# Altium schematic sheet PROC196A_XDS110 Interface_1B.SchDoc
size 431 x 279 mm; Date: Not shown in title block; ApprovedBy: Not shown in title block; CheckedBy: Not shown in title block; Author: Not shown in title block; CompanyName: Not shown in title block; Engineer: Not shown in title block; Organization: Not shown in title block; Address1: Not shown in title block; Address2: Not shown in title block; Address3: Not shown in title block; Address4: Not shown in title block; DocumentNumber: 19; Revision: Use project parameter SCH_Rev; SheetNumber: 19; SheetTotal: 25; PageSetup: Record=PageOptions¦CenterHorizontal=True¦CenterVertical=True¦PrintScale=1.00¦XCorrection=1.00¦YCorrection=1.00¦PrintKind=0¦BorderSize=5000000¦LeftOffset=0¦BottomOffset=0¦Orientation=2¦PaperLength=1000¦PaperWidth=1000¦Scale=100¦PaperSource=15¦PrintQuality=600¦MediaType=1¦DitherType=10¦PaperKind=Letter¦PrintScaleMode=1
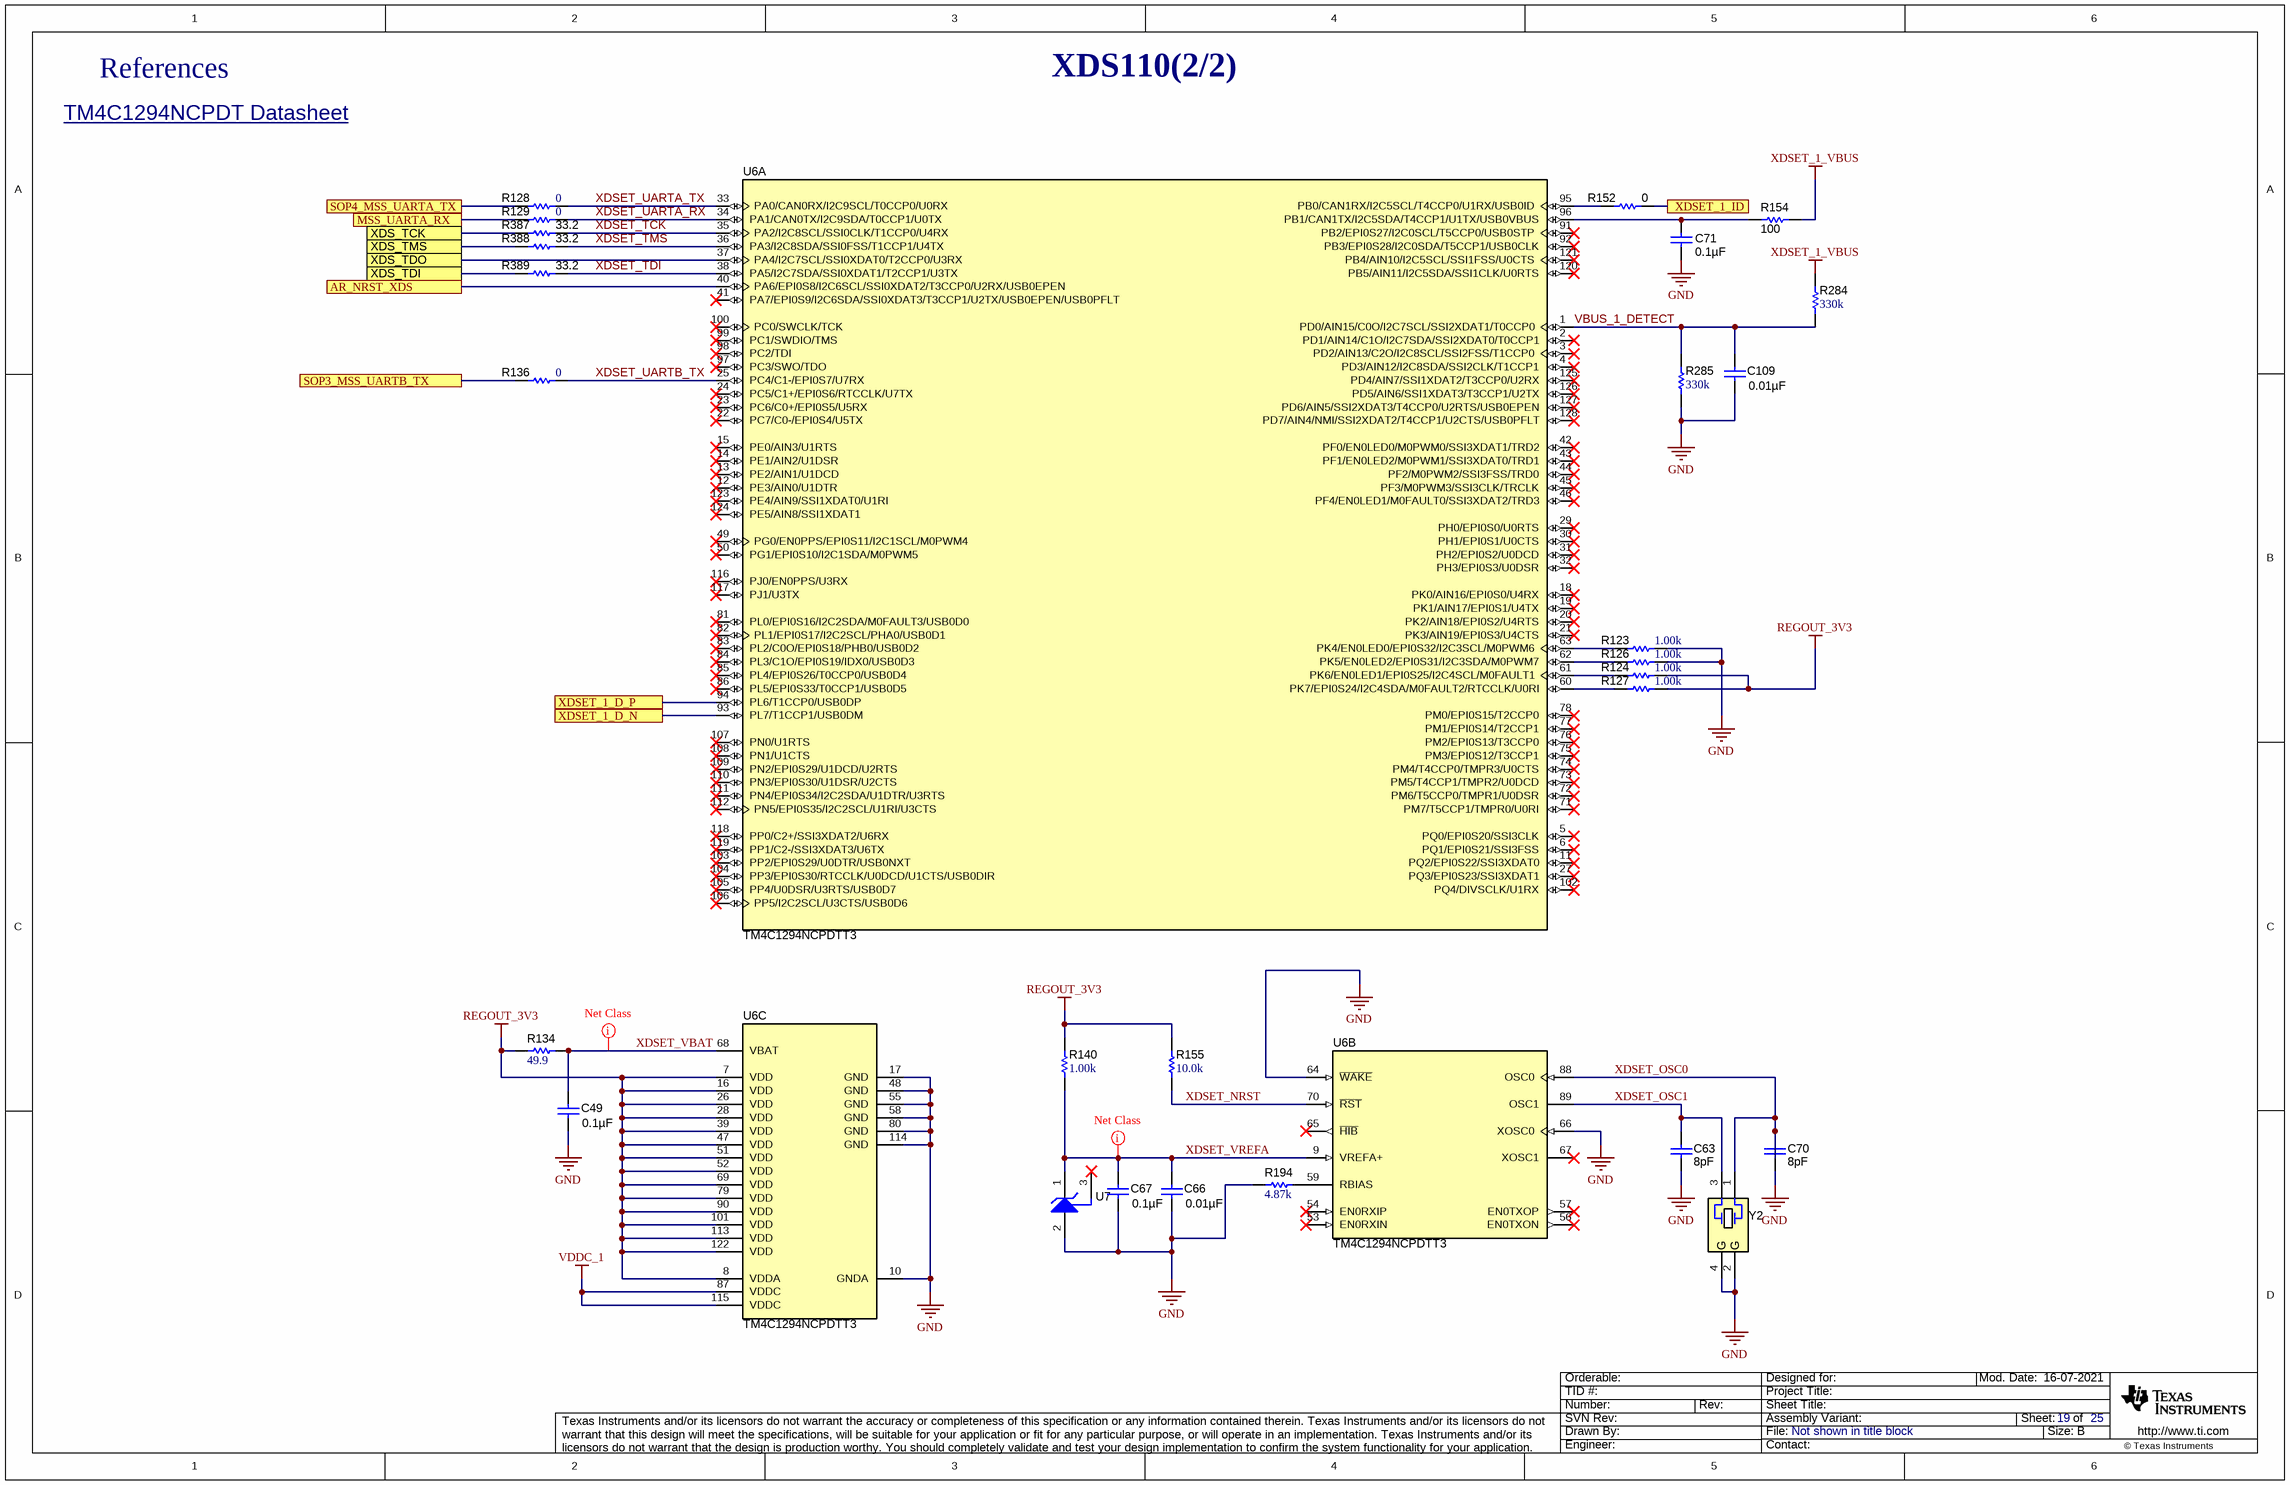
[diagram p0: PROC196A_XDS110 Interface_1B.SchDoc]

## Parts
C49  ValueDisplayed: 0.1µF  [0402L]  (hidden comment: C0402C104K8RACTU)
C63  Cap_F: 8pF  [0402L]  (hidden comment: GCM1555C1H8R0DA16D)
C66  ValueDisplayed: 0.01µF  [0402L]  (hidden comment: C0402C103K4RACTU)
C67  ValueDisplayed: 0.1µF  [0402L]  (hidden comment: C0402C104K8RACTU)
C70  Cap_F: 8pF  [0402L]  (hidden comment: GCM1555C1H8R0DA16D)
C71  ValueDisplayed: 0.1µF  [0402L]  (hidden comment: C0402C104K8RACTU)
C109  ValueDisplayed: 0.01µF  [0402L]  (hidden comment: C0402C103K4RACTU)
R123  ValueDisplayed: 1.00k  [0402L]  (hidden comment: CRCW04021K00FKED)
R124  ValueDisplayed: 1.00k  [0402L]  (hidden comment: CRCW04021K00FKED)
R126  ValueDisplayed: 1.00k  [0402L]  (hidden comment: CRCW04021K00FKED)
R127  ValueDisplayed: 1.00k  [0402L]  (hidden comment: CRCW04021K00FKED)
R128  ValueDisplayed: 0  [0402L]  (hidden comment: ERJ-2GE0R00X)
R129  ValueDisplayed: 0  [0402L]  (hidden comment: ERJ-2GE0R00X)
R134  ValueDisplayed: 49.9  [0402L]  (hidden comment: CRCW040249R9FKED)
R136  ValueDisplayed: 0  [0402L]  (hidden comment: ERJ-2GE0R00X)
R140  ValueDisplayed: 1.00k  [0402L]  (hidden comment: CRCW04021K00FKED)
R152  ValueDisplayed: 0  [0402L]  (hidden comment: ERJ-2GE0R00X)
R154  ValueDisplayed: 100  [0402L]  (hidden comment: ERJ-2GEJ101X)
R155  ValueDisplayed: 10.0k  [0402L]  (hidden comment: CRCW040210K0FKED)
R194  ValueDisplayed: 4.87k  [0402L]  (hidden comment: CRCW04024K87FKED)
R284  ValueDisplayed: 330k  [0402L]  (hidden comment: CRCW0402330KFKED)
R285  ValueDisplayed: 330k  [0402L]  (hidden comment: CRCW0402330KFKED)
R387  ValueDisplayed: 33.2  [0402L]  (hidden comment: CRCW040233R2FKED)
R388  ValueDisplayed: 33.2  [0402L]  (hidden comment: CRCW040233R2FKED)
R389  ValueDisplayed: 33.2  [0402L]  (hidden comment: CRCW040233R2FKED)
U6  TM4C1294NCPDTT3  [PDT0128A]  (parts A,B,C of 3)
U7  LM4040C25QDBZR  [DBZ0003A_N]  (value not drawn)
Y2  NX3225SA-16.000M-STD-CRS-2  [NDK_NX3225SA]  (value not drawn)

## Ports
AR_NRST_XDS, MSS_UARTA_RX, SOP3_MSS_UARTB_TX, SOP4_MSS_UARTA_TX, XDS_TCK, XDS_TDI, XDS_TDO, XDS_TMS, XDSET_1_D_N, XDSET_1_D_P, XDSET_1_ID

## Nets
GND: C49.2 C63.1 C66.1 C67.1 C70.2 C71.1 C109.1 R123.2 R126.2 R194.1 R285.1 U6.10(GNDA) U6.17(GND) U6.48(GND) U6.55(GND) U6.58(GND) U6.64(~{WAKE}) U6.66(XOSC0) U6.80(GND) U6.114(GND) U7.2(ANODE) Y2.2(GND) Y2.4(GND)
REGOUT_3V3: R124.2 R127.2 R134.2 R140.2 R155.2 U6.7(VDD) U6.8(VDDA) U6.16(VDD) U6.26(VDD) U6.28(VDD) U6.39(VDD) U6.47(VDD) U6.51(VDD) U6.52(VDD) U6.69(VDD) U6.79(VDD) U6.90(VDD) U6.101(VDD) U6.113(VDD) U6.122(VDD)
VDDC_1: U6.87(VDDC) U6.115(VDDC)
XDSET_1_VBUS: R154.2 R284.2
AR_NRST_XDS: U6.40(PA6/EPI0S8/I2C6SCL/SSI0XDAT2/T3CCP0/U2RX/USB0EPEN) ; port AR_NRST_XDS
MSS_UARTA_RX: R129.1 ; port MSS_UARTA_RX
SOP3_MSS_UARTB_TX: R136.1 ; port SOP3_MSS_UARTB_TX
SOP4_MSS_UARTA_TX: R128.1 ; port SOP4_MSS_UARTA_TX
VBUS_1_DETECT: C109.2 R284.1 R285.2 U6.1(PD0/AIN15/C0O/I2C7SCL/SSI2XDAT1/T0CCP0)
XDS_TCK: R387.1 ; port XDS_TCK
XDS_TDI: R389.1 ; port XDS_TDI
XDS_TDO: U6.37(PA4/I2C7SCL/SSI0XDAT0/T2CCP0/U3RX) ; port XDS_TDO
XDS_TMS: R388.1 ; port XDS_TMS
XDSET_1_D_N: U6.93(PL7/T1CCP1/USB0DM) ; port XDSET_1_D_N
XDSET_1_D_P: U6.94(PL6/T1CCP0/USB0DP) ; port XDSET_1_D_P
XDSET_1_ID: R152.1 ; port XDSET_1_ID
XDSET_NRST: R155.1 U6.70(~{RST})
XDSET_OSC0: C70.1 U6.88(OSC0) Y2.1
XDSET_OSC1: C63.2 U6.89(OSC1) Y2.3
XDSET_TCK: R387.2 U6.35(PA2/I2C8SCL/SSI0CLK/T1CCP0/U4RX)
XDSET_TDI: R389.2 U6.38(PA5/I2C7SDA/SSI0XDAT1/T2CCP1/U3TX)
XDSET_TMS: R388.2 U6.36(PA3/I2C8SDA/SSI0FSS/T1CCP1/U4TX)
XDSET_UARTA_RX: R129.2 U6.34(PA1/CAN0TX/I2C9SDA/T0CCP1/U0TX)
XDSET_UARTA_TX: R128.2 U6.33(PA0/CAN0RX/I2C9SCL/T0CCP0/U0RX)
XDSET_UARTB_TX: R136.2 U6.25(PC4/C1-/EPI0S7/U7RX)
XDSET_VBAT: C49.1 R134.1 U6.68(VBAT)
XDSET_VREFA: C66.2 C67.2 R140.1 U6.9(VREFA+) U7.1(CATHODE)
NetC71_2: C71.2 R154.1 U6.96(PB1/CAN1TX/I2C5SDA/T4CCP1/U1TX/USB0VBUS)
NetR123_1: R123.1 U6.63(PK4/EN0LED0/EPI0S32/I2C3SCL/M0PWM6)
NetR124_1: R124.1 U6.61(PK6/EN0LED1/EPI0S25/I2C4SCL/M0FAULT1)
NetR126_1: R126.1 U6.62(PK5/EN0LED2/EPI0S31/I2C3SDA/M0PWM7)
NetR127_1: R127.1 U6.60(PK7/EPI0S24/I2C4SDA/M0FAULT2/RTCCLK/U0RI)
NetR152_2: R152.2 U6.95(PB0/CAN1RX/I2C5SCL/T4CCP0/U1RX/USB0ID)
NetR194_2: R194.2 U6.59(RBIAS)

Not connected (* = marked no-connect by the designer): U6 2(PD1/AIN14/C1O/I2C7SDA/SSI2XDAT0/T0CCP1)* 3(PD2/AIN13/C2O/I2C8SCL/SSI2FSS/T1CCP0)* 4(PD3/AIN12/I2C8SDA/SSI2CLK/T1CCP1)* 5(PQ0/EPI0S20/SSI3CLK)* 6(PQ1/EPI0S21/SSI3FSS)* 11(PQ2/EPI0S22/SSI3XDAT0)* 12(PE3/AIN0/U1DTR)* 13(PE2/AIN1/U1DCD)* 14(PE1/AIN2/U1DSR)* 15(PE0/AIN3/U1RTS)* 18(PK0/AIN16/EPI0S0/U4RX)* 19(PK1/AIN17/EPI0S1/U4TX)* 20(PK2/AIN18/EPI0S2/U4RTS)* 21(PK3/AIN19/EPI0S3/U4CTS)* 22(PC7/C0-/EPI0S4/U5TX)* 23(PC6/C0+/EPI0S5/U5RX)* 24(PC5/C1+/EPI0S6/RTCCLK/U7TX)* 27(PQ3/EPI0S23/SSI3XDAT1)* 29(PH0/EPI0S0/U0RTS)* 30(PH1/EPI0S1/U0CTS)* 31(PH2/EPI0S2/U0DCD)* 32(PH3/EPI0S3/U0DSR)* 41(PA7/EPI0S9/I2C6SDA/SSI0XDAT3/T3CCP1/U2TX/USB0EPEN/USB0PFLT)* 42(PF0/EN0LED0/M0PWM0/SSI3XDAT1/TRD2)* 43(PF1/EN0LED2/M0PWM1/SSI3XDAT0/TRD1)* 44(PF2/M0PWM2/SSI3FSS/TRD0)* 45(PF3/M0PWM3/SSI3CLK/TRCLK)* 46(PF4/EN0LED1/M0FAULT0/SSI3XDAT2/TRD3)* 49(PG0/EN0PPS/EPI0S11/I2C1SCL/M0PWM4)* 50(PG1/EPI0S10/I2C1SDA/M0PWM5)* 53(EN0RXIN)* 54(EN0RXIP)* 56(EN0TXON)* 57(EN0TXOP)* 65(~{HIB})* 67(XOSC1)* 71(PM7/T5CCP1/TMPR0/U0RI)* 72(PM6/T5CCP0/TMPR1/U0DSR)* 73(PM5/T4CCP1/TMPR2/U0DCD)* 74(PM4/T4CCP0/TMPR3/U0CTS)* 75(PM3/EPI0S12/T3CCP1)* 76(PM2/EPI0S13/T3CCP0)* 77(PM1/EPI0S14/T2CCP1)* 78(PM0/EPI0S15/T2CCP0)* 81(PL0/EPI0S16/I2C2SDA/M0FAULT3/USB0D0)* 82(PL1/EPI0S17/I2C2SCL/PHA0/USB0D1)* 83(PL2/C0O/EPI0S18/PHB0/USB0D2)* 84(PL3/C1O/EPI0S19/IDX0/USB0D3)* 85(PL4/EPI0S26/T0CCP0/USB0D4)* 86(PL5/EPI0S33/T0CCP1/USB0D5)* 91(PB2/EPI0S27/I2C0SCL/T5CCP0/USB0STP)* 92(PB3/EPI0S28/I2C0SDA/T5CCP1/USB0CLK)* 97(PC3/SWO/TDO)* 98(PC2/TDI)* 99(PC1/SWDIO/TMS)* 100(PC0/SWCLK/TCK)* 102(PQ4/DIVSCLK/U1RX)* 103(PP2/EPI0S29/U0DTR/USB0NXT)* 104(PP3/EPI0S30/RTCCLK/U0DCD/U1CTS/USB0DIR)* 105(PP4/U0DSR/U3RTS/USB0D7)* 106(PP5/I2C2SCL/U3CTS/USB0D6)* 107(PN0/U1RTS)* 108(PN1/U1CTS)* 109(PN2/EPI0S29/U1DCD/U2RTS)* 110(PN3/EPI0S30/U1DSR/U2CTS)* 111(PN4/EPI0S34/I2C2SDA/U1DTR/U3RTS)* 112(PN5/EPI0S35/I2C2SCL/U1RI/U3CTS)* 116(PJ0/EN0PPS/U3RX)* 117(PJ1/U3TX)* 118(PP0/C2+/SSI3XDAT2/U6RX)* 119(PP1/C2-/SSI3XDAT3/U6TX)* 120(PB5/AIN11/I2C5SDA/SSI1CLK/U0RTS)* 121(PB4/AIN10/I2C5SCL/SSI1FSS/U0CTS)* 123(PE4/AIN9/SSI1XDAT0/U1RI)* 124(PE5/AIN8/SSI1XDAT1)* 125(PD4/AIN7/SSI1XDAT2/T3CCP0/U2RX)* 126(PD5/AIN6/SSI1XDAT3/T3CCP1/U2TX)* 127(PD6/AIN5/SSI2XDAT3/T4CCP0/U2RTS/USB0EPEN)* 128(PD7/AIN4/NMI/SSI2XDAT2/T4CCP1/U2CTS/USB0PFLT)*; U7 3(NC)*

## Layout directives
net class PWR: XDSET_VBAT, XDSET_VREFA

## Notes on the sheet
- References
- XDS110(2/2)
- TM4C1294NCPDT Datasheet <http://www.ti.com/lit/ds/symlink/tm4c1294ncpdt.pdf>

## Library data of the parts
C49 = CMP-0078241-1: CAP, CERM, 0.1 µF, 10 V,+/- 10%, X7R, 0402; Manufacturer: Kemet; TaMin_C: -55°C; Polarized: N; SizeAreaWB_mm2: 3; U/M: EA; Value: 0.1uF; TaMax_C: 125°C; SizeZ_mm: 0.6; SizeX_mm: 1; SizeY_mm: 0.5; Cap_Case: 0402; Value2: 10V; CompType: Capacitor; Cap_F: 100nF; AEC Category: Q200
C63 C70 = CMP-0087060-3: Cap Ceramic 8pF 50V C0G 0.5pF SMD 0402 125C Paper T/R; Manufacturer: Murata Electronics North America; TempCo: 30ppm/°C; AEC Qualified: Yes; AEC Grade: Grade 1; SizeZ_mm: 0.55mm
C66 C109 = CMP-0078218-1: CAP, CERM, 0.01 µF, 16 V,+/- 10%, X7R, 0402; Manufacturer: Kemet; TaMin_C: -55°C; Polarized: N; Green_Lifecycle: Active; SizeAreaWB_mm2: 3; Green_REACh: Passed; U/M: EA; Value: 0.01uF; TaMax_C: 125°C; SizeZ_mm: 0.6; SizeX_mm: 1; SizeY_mm: 0.5; Cap_Case: 0402; Value2: 16V; Cap_F: 10nF; AEC Category: Q200
C67 C71 = CMP-0078241-1: CAP, CERM, 0.1 µF, 10 V,+/- 10%, X7R, 0402; Manufacturer: Kemet; TaMin_C: -55°C; Polarized: N; SizeAreaWB_mm2: 3; U/M: EA; Value: 0.1uF; TaMax_C: 125°C; SizeZ_mm: 0.6; SizeX_mm: 1; SizeY_mm: 0.5; Cap_Case: 0402; Value2: 10V; Cap_F: 100nF; AEC Category: Q200
R123 R124 R126 R127 R140 = CMP-0026071-3: RES, 1.00 k, 1%, 0.063 W, AEC-Q200 Grade 0, 0402; Manufacturer: Vishay-Dale; Power_W: 63mW; TempCo: 100 ppm/C; Value_Code: 1k00; Value: 1.00k; EIA_Code: E96; Res_ohm: 1k; SizeX_mm: 1; SizeY_mm: 0.5; SizeZ_mm: 0.6; Value2: 0.063W; AEC Qualified: Y; VDC_V: 50V; AEC Category: Q200; AEC Grade: 0
R128 R129 R136 = CMP-0026992-3: RES, 0, 5%, 0.1 W, AEC-Q200 Grade 0, 0402; Manufacturer: Panasonic; Power_W: 100mW; TempCo: 600 ppm/C; Value_Code: 0000; Value: 0; EIA_Code: E24; SizeX_mm: 1; SizeY_mm: 0.5; SizeZ_mm: 0.6; Value2: 0.1W; CompType: Resistor; AEC Qualified: Y; VDC_V: 50V; AEC Category: Q200; SizeAreaWB_mm2: 3; INSTALLATION: DNP
R134 = CMP-0026404-2: RES, 49.9, 1%, 0.063 W, AEC-Q200 Grade 0, 0402; Manufacturer: Vishay-Dale; Power_W: 63mW; TempCo: 100 ppm/C; Value_Code: 49R9; Value: 49.9; EIA_Code: E96; SizeX_mm: 1; SizeY_mm: 0.5; SizeZ_mm: 0.6; Value2: 0.063W; AEC Qualified: Y; VDC_V: 50V; AEC Category: Q200; AEC Grade: 0
R152 = CMP-0026992-3: RES, 0, 5%, 0.1 W, AEC-Q200 Grade 0, 0402; Manufacturer: Panasonic; Power_W: 100mW; TempCo: 600 ppm/C; Value_Code: 0000; Value: 0; EIA_Code: E24; SizeX_mm: 1; SizeY_mm: 0.5; SizeZ_mm: 0.6; Value2: 0.1W; AEC Qualified: Y; VDC_V: 50V; AEC Category: Q200; SizeAreaWB_mm2: 3
R154 = CMP-0026993-2: RES, 100, 5%, 0.1 W, AEC-Q200 Grade 0, 0402; Manufacturer: Panasonic; Power_W: 100mW; TempCo: 200 ppm/C; Value_Code: 100R; U/M: EA; Value: 100; EIA_Code: E24; SizeX_mm: 1; SizeY_mm: 0.5; SizeZ_mm: 0.6; Value2: 0.1W; AEC Qualified: Y; AEC Grade: 0; AEC Category: Q200
R155 = CMP-0025958-3: RES, 10.0 k, 1%, 0.063 W, AEC-Q200 Grade 0, 0402; Manufacturer: Vishay-Dale; Power_W: 63mW; TempCo: 100 ppm/C; Value_Code: 10k0; Value: 10.0k; EIA_Code: E96; Res_ohm: 10k; SizeX_mm: 1; SizeY_mm: 0.5; SizeZ_mm: 0.6; Value2: 0.063W; AEC Qualified: Y; VDC_V: 50V; AEC Category: Q200; AEC Grade: 0
R194 = CMP-0026413-2: RES, 4.87 k, 1%, 0.063 W, AEC-Q200 Grade 0, 0402; Manufacturer: Vishay-Dale; Power_W: 63mW; TempCo: 100 ppm/C; Value_Code: 4k87; Value: 4.87k; EIA_Code: E96; SizeX_mm: 1; SizeY_mm: 0.5; SizeZ_mm: 0.6; Value2: 0.063W; AEC Qualified: Y; VDC_V: 50V; AEC Category: Q200; AEC Grade: 0
R284 R285 = CMP-0078210-2: RES, 330 k, 1%, 0.063 W, AEC-Q200 Grade 0, 0402; Manufacturer: Vishay-Dale; SizeArea_mm2: 0.5; AEC Qualified: Y; AEC Category: Q200; Value: 330k; SizeZ_mm: 0.6; TempCo: 100 ppm/C; AEC Grade: 0; Power_W: 63mW; VDC_V: 50V; Value2: 0.063W; SizeX_mm: 1
R387-R389 = CMP-0026299-2: RES, 33.2, 1%, 0.063 W, AEC-Q200 Grade 0, 0402; Manufacturer: Vishay-Dale; Power_W: 63mW; TempCo: 100 ppm/C; Value_Code: 33R2; Value: 33.2; EIA_Code: E96; SizeX_mm: 1; SizeY_mm: 0.5; SizeZ_mm: 0.6; Value2: 0.063W; AEC Qualified: Y; VDC_V: 50V; AEC Category: Q200; AEC Grade: 0
U6 = CMP-0029856-2: Tiva C Series Microcontroller, 1024 KB Flash, 256 KB SRAM, 12 Bit, 20 Channels, -40 to 105 degC, 128-Pin TQFP (PDT), Green (RoHS & no Sb/Br), Tray; Manufacturer: Texas Instruments; ADC Channels: 20; CPU: ARM Cortex-M4; Flash: 1024 KB; ADC Resolution: 12 Bits; Max Speed: 120 MHz; SRAM: 256 KB; SizeAreaWB_mm2: 324.0; SizeArea_mm2: 256.0; SizeX_mm: 16.0; SizeZ_mm: 1.2; CompType: IC
U7 = CMP-0033001-1: Precision Micropower Shunt Voltage Reference, 0.5% accuracy, 2.5 V, 15 ppm / degC, 15 mA, -40 to 125 degC, 3-pin SOT-23 (DBZ), Green (RoHS & no Sb/Br); Manufacturer: Texas Instruments; Initial Accuracy @ 25/deg C(%): 0.5; Temp Coeff(Typ)(ppm/ degree C): 15; Temp Coeff(Max)(ppm/ degree C): 100; Rating: Catalog; Min Iz for Regulation(uA): 75; VO(V): 2.5
Y2 = CMP-0078214-2: Crystal, 16 MHz, 15 ppm, 8 pF, AEC-Q200 Grade 1, SMD; Manufacturer: NDK; TaMin_C: -40°C; Frequency Tolerance: 10 ppm; Frequency Stability: 150 ppm; Load Capacitance: 7.36 pF; Frequency_Fixed: 16MHz; TaMax_C: 125°C; AEC Qualified: N; AEC Grade: 1; AEC Category: Q200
